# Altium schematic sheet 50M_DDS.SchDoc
size B
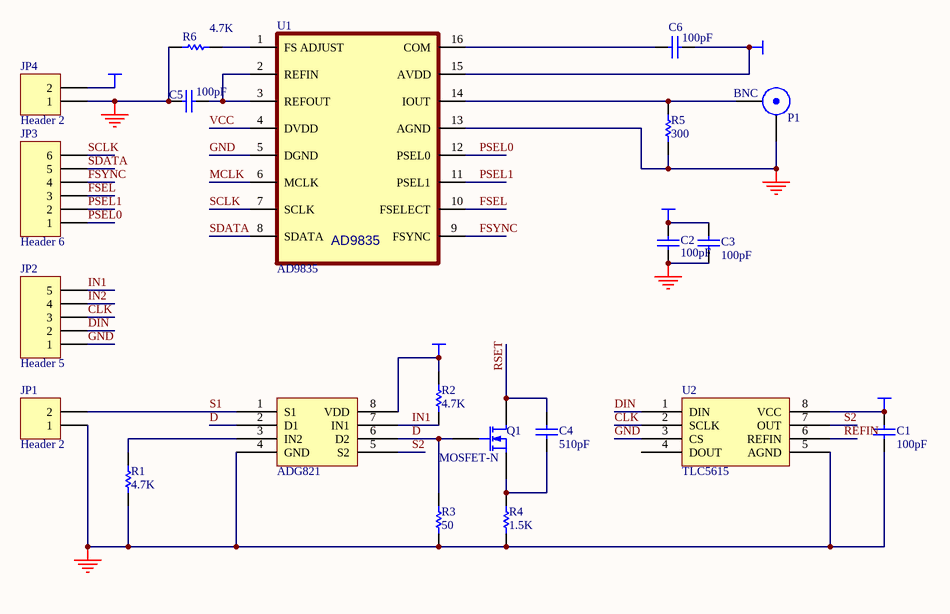
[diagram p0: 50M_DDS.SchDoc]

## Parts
?  ADG821
C1  100pF  [RAD-0.3]
C2  100pF  [RAD-0.3]
C3  100pF  [RAD-0.3]
C4  510pF  [RAD-0.3]
C5  100pF  [RAD-0.3]
C6  100pF  [RAD-0.3]
JP1  Header 2  [HDR1X2]
JP2  Header 5  [HDR1X5]
JP3  Header 6  [HDR1X6]
JP4  Header 2  [HDR1X2]
P1  BNC  [BNC_RA CON]
Q1  MOSFET-N  [BCY-W3/H.8]
R1  4.7K  [AXIAL-0.3]
R2  4.7K  [AXIAL-0.3]
R3  50  [AXIAL-0.3]
R4  1.5K  [AXIAL-0.3]
R5  300  [AXIAL-0.3]
R6  4.7K  [AXIAL-0.3]
U1  AD9835  [TSSOP-16]
U2  TLC5615  [SO-8]

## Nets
GND: ?.4(GND) C1.1 C2.1 C3.1 C5.1 JP1.1 JP2.1 JP4.1 P1.1(X) R1.2 R3.1 R4.1 R5.1 R6.1 U1.5(DGND) U1.13(AGND) U2.3(CS) U2.5(AGND)
VCC: ?.8(VDD) C1.2 C2.2 C3.2 C6.1 JP4.2 R2.2 U1.4(DVDD) U1.15(AVDD) U2.8(VCC)
CLK: JP2.3 U2.2(SCLK)
D: ?.2(D1) ?.6(D2) Q1.2(G) R3.2
DIN: JP2.2 U2.1(DIN)
FSEL: JP3.3 U1.10(FSELECT)
FSYNC: JP3.4 U1.9(FSYNC)
IN1: ?.7(IN1) JP2.5 R2.1
IN2: JP2.4
MCLK: U1.6(MCLK)
PSEL0: JP3.1 U1.12(PSEL0)
PSEL1: JP3.2 U1.11(PSEL1)
REFIN: U2.6(REFIN)
RSET: C4.2 Q1.1(D)
S1: ?.1(S1) JP1.2
S2: ?.5(S2) U2.7(OUT)
SCLK: JP3.6 U1.7(SCLK)
SDATA: JP3.5 U1.8(SDATA)
Net?_3: ?.3(IN2) R1.1
NetC4_1: C4.1 Q1.3(S) R4.2
NetC5_2: C5.2 U1.2(REFIN) U1.3(REFOUT)
NetC6_2: C6.2 U1.16(COM)
NetP1_2: P1.2(Y) R5.2 U1.14(IOUT)
NetR6_2: R6.2 U1.1(FS_ADJUST)

Not connected (* = marked no-connect by the designer): U2 4(DOUT)

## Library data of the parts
C1-C6 = Cap: Capacitor; Manufacturer: Generic Components; Class I: Passive
JP1 JP4 = Header 2: Header, 2-Pin; Manufacturer: Generic Components; Class I: Connector
JP2 = Header 5: Header, 5-Pin; Manufacturer: Generic Components; Class I: Connector
JP3 = Header 6: Header, 6-Pin; Manufacturer: Generic Components; Class I: Connector
P1 = BNC: BNC Elbow Connector; Manufacturer: Generic Components; Class II: RF Coaxial
Q1 = MOSFET-N: N-Channel MOSFET; Manufacturer: Generic Components; Class I: Discrete; Class II: MOSFET - Low Power
R1-R6 = Res1: Resistor; Manufacturer: Generic Components; Class I: Passive
U1 = AD9835: 50 MHz CMOS / Complete DDS
U2 = TLC5615: 10bit DA Convertor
